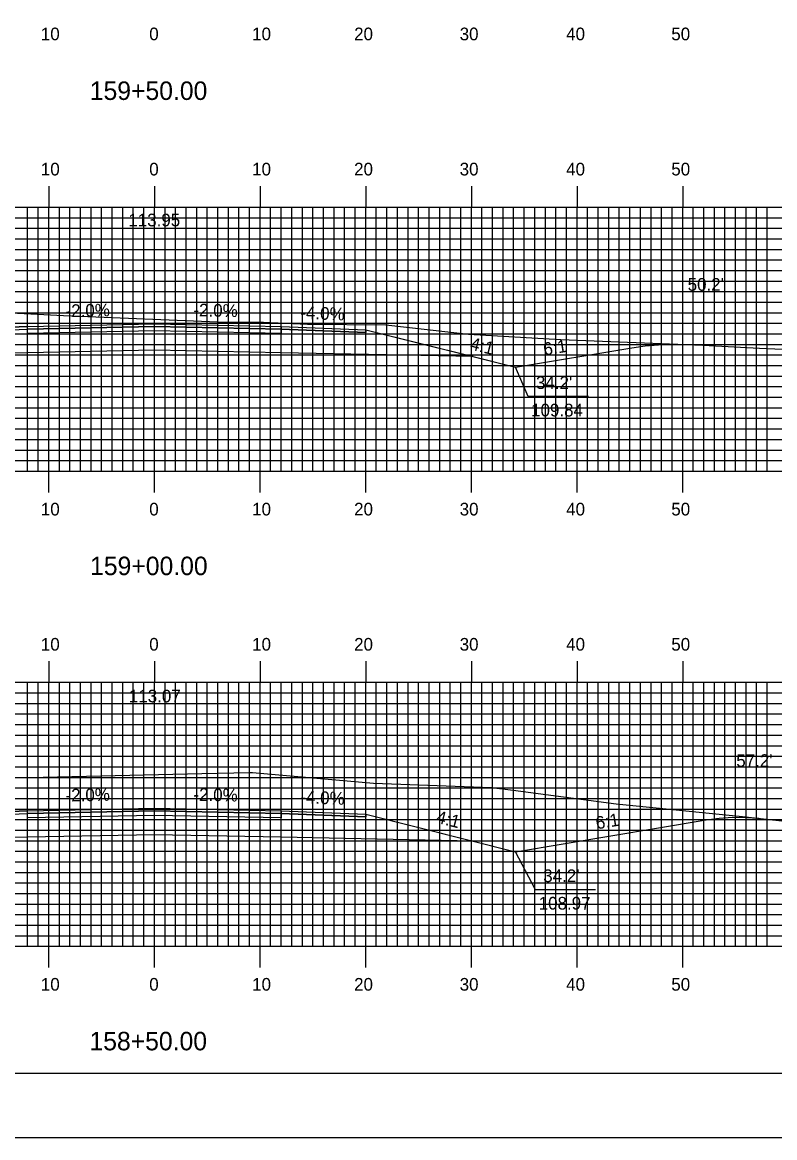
# Model space of a CAD drawing. Extents: x 1779893 to 1780236, y 442591 to 442811.
# Drawn here: x 1780045.9 to 1780117.1, y 442590.5 to 442696.2 of the extents above; entities that cross this region are included whole.
import ezdxf

# ---------------------------------------------------------------- set-up
doc = ezdxf.new("R2010")
doc.units = 0
for name, color, linetype in [('ANNOTATION', 7, 'Continuous'), ('BORDER', 7, 'Continuous'), ('D_Roadway_Centerline', 7, 'Continuous'), ('D_Roadway_Centerline_Text', 7, 'Continuous'), ('D_Roadway_Edge_Shoulder', 7, 'Continuous'), ('D_Roadway_Edge_TW', 7, 'Continuous'), ('D_Roadway_Pavement', 7, 'Continuous'), ('D_Roadway_SlopeLines', 7, 'Continuous'), ('D_Roadway_SubGrade', 7, 'Continuous'), ('D_Text_Standard', 7, 'Continuous'), ('H_V ANNOTATION', 7, 'Continuous'), ('MAJOR', 7, 'Continuous'), ('MINOR', 7, 'Continuous'), ('PLOT BOUNDARY', 7, 'Continuous'), ('S_Roadway_Centerline', 7, 'Continuous')]:
    doc.layers.add(name, color=color, linetype=linetype)

msp = doc.modelspace()

# ---------------------------------------------------------------- linework, layer by layer
at = {"layer": 'ANNOTATION'}
for points in [[(1780099.43, 442660.73), (1780093.74, 442660.73), (1780092.53, 442663.51)], [(1780100.12, 442614.02), (1780094.42, 442614.02), (1780092.53, 442617.63)]]:
    msp.add_lwpolyline(points, dxfattribs=at)
at = {"layer": 'BORDER'}
msp.add_lwpolyline([(1779908.76, 442596.67), (1780228.76, 442596.67), (1780228.76, 442806.67), (1779908.76, 442806.67)], close=True, dxfattribs=at)
at = {"layer": 'D_Roadway_Centerline'}
for points in [[(1779986.66, 442669.34), (1779987.91, 442669.32), (1779989.16, 442669.24), (1779990.41, 442669.11), (1779991.66, 442668.93), (1780024.18, 442663.51), (1780028.18, 442664.51), (1780038.36, 442667.05), (1780046.36, 442667.37), (1780058.36, 442667.61), (1780070.36, 442667.37), (1780078.36, 442667.05), (1780088.53, 442664.51), (1780092.53, 442663.51), (1780103.56, 442665.35), (1780104.81, 442665.52), (1780106.06, 442665.64), (1780107.31, 442665.68), (1780108.56, 442665.67)], [(1779987.48, 442623.37), (1779988.73, 442623.33), (1779989.98, 442623.24), (1779991.23, 442623.1), (1779992.48, 442622.92), (1780024.18, 442617.63), (1780028.18, 442618.63), (1780038.36, 442621.18), (1780046.36, 442621.5), (1780058.36, 442621.74), (1780070.36, 442621.5), (1780078.36, 442621.18), (1780088.53, 442618.63), (1780092.53, 442617.63), (1780110.57, 442620.64), (1780111.82, 442620.81), (1780113.07, 442620.89), (1780114.32, 442620.88), (1780115.57, 442620.79)]]:
    msp.add_lwpolyline(points, dxfattribs=at)
at = {"layer": 'D_Roadway_Edge_Shoulder'}
for points in [[(1780046.36, 442667.37), (1780038.36, 442667.05), (1780038.36, 442666.8), (1780046.36, 442667.12)], [(1780070.36, 442667.37), (1780078.36, 442667.05), (1780078.36, 442666.8), (1780070.36, 442667.12)], [(1780046.36, 442621.5), (1780038.36, 442621.18), (1780038.36, 442620.93), (1780046.36, 442621.25)], [(1780070.36, 442621.5), (1780078.36, 442621.18), (1780078.36, 442620.93), (1780070.36, 442621.25)]]:
    msp.add_lwpolyline(points, close=True, dxfattribs=at)
at = {"layer": 'D_Roadway_Edge_TW'}
for points in [[(1780046.36, 442667.12), (1780046.36, 442667.37), (1780058.36, 442667.61), (1780070.36, 442667.37), (1780070.36, 442667.12), (1780058.36, 442667.36)], [(1780046.36, 442621.25), (1780046.36, 442621.5), (1780058.36, 442621.74), (1780070.36, 442621.5), (1780070.36, 442621.25), (1780058.36, 442621.49)]]:
    msp.add_lwpolyline(points, close=True, dxfattribs=at)
at = {"layer": 'D_Roadway_Pavement'}
for points in [[(1780046.36, 442666.71), (1780046.36, 442667.12), (1780058.36, 442667.36), (1780070.36, 442667.12), (1780070.36, 442666.71), (1780058.36, 442666.95)], [(1780046.36, 442620.83), (1780046.36, 442621.25), (1780058.36, 442621.49), (1780070.36, 442621.25), (1780070.36, 442620.83), (1780058.36, 442621.07)]]:
    msp.add_lwpolyline(points, close=True, dxfattribs=at)
at = {"layer": 'D_Roadway_SlopeLines'}
for points in [[(1780078.36, 442667.05), (1780092.53, 442663.51)], [(1780092.53, 442663.51), (1780103.56, 442665.35), (1780104.81, 442665.52), (1780106.06, 442665.64), (1780107.31, 442665.68), (1780108.56, 442665.67)], [(1780078.36, 442621.18), (1780092.53, 442617.63)], [(1780092.53, 442617.63), (1780110.57, 442620.64), (1780111.82, 442620.81), (1780113.07, 442620.89), (1780114.32, 442620.88), (1780115.57, 442620.79)]]:
    msp.add_lwpolyline(points, dxfattribs=at)
at = {"layer": 'D_Roadway_SubGrade'}
for points in [[(1780046.36, 442664.87), (1780028.18, 442664.51), (1780038.36, 442667.05), (1780038.36, 442666.8), (1780046.36, 442667.12), (1780058.36, 442667.36), (1780070.36, 442667.12), (1780078.36, 442666.8), (1780078.36, 442667.05), (1780088.53, 442664.51), (1780070.36, 442664.87), (1780058.36, 442665.11)], [(1780046.36, 442619), (1780028.18, 442618.63), (1780038.36, 442621.18), (1780038.36, 442620.93), (1780046.36, 442621.25), (1780058.36, 442621.49), (1780070.36, 442621.25), (1780078.36, 442620.93), (1780078.36, 442621.18), (1780088.53, 442618.63), (1780070.36, 442619), (1780058.36, 442619.24)]]:
    msp.add_lwpolyline(points, close=True, dxfattribs=at)
at = {"layer": 'MAJOR'}
for p, q in [((1780048.36, 442680.67), (1780048.36, 442678.67)), ((1780058.36, 442680.67), (1780058.36, 442678.67)), ((1780068.36, 442680.67), (1780068.36, 442678.67)), ((1780078.36, 442680.67), (1780078.36, 442678.67)), ((1780088.36, 442680.67), (1780088.36, 442678.67)), ((1780098.36, 442680.67), (1780098.36, 442678.67)), ((1780108.36, 442680.67), (1780108.36, 442678.67)), ((1779918.36, 442678.67), (1780198.36, 442678.67)), ((1779918.36, 442678.67), (1780198.36, 442678.67)), ((1780048.36, 442653.67), (1780048.36, 442678.67)), ((1780058.36, 442653.67), (1780058.36, 442678.67)), ((1780068.36, 442653.67), (1780068.36, 442678.67)), ((1780078.36, 442653.67), (1780078.36, 442678.67)), ((1780088.36, 442653.67), (1780088.36, 442678.67)), ((1780098.36, 442653.67), (1780098.36, 442678.67)), ((1780108.36, 442653.67), (1780108.36, 442678.67)), ((1779918.36, 442673.67), (1780198.36, 442673.67)), ((1779918.36, 442668.67), (1780198.36, 442668.67)), ((1779918.36, 442663.67), (1780198.36, 442663.67)), ((1779918.36, 442658.67), (1780198.36, 442658.67)), ((1779918.36, 442653.67), (1780198.36, 442653.67)), ((1779918.36, 442653.67), (1780198.36, 442653.67)), ((1780048.36, 442651.66), (1780048.36, 442653.67)), ((1780058.36, 442651.66), (1780058.36, 442653.67)), ((1780068.36, 442651.66), (1780068.36, 442653.67)), ((1780078.36, 442651.66), (1780078.36, 442653.67)), ((1780088.36, 442651.66), (1780088.36, 442653.67)), ((1780098.36, 442651.66), (1780098.36, 442653.67)), ((1780108.36, 442651.66), (1780108.36, 442653.67)), ((1780048.36, 442635.67), (1780048.36, 442633.67)), ((1780058.36, 442635.67), (1780058.36, 442633.67)), ((1780068.36, 442635.67), (1780068.36, 442633.67)), ((1780078.36, 442635.67), (1780078.36, 442633.67)), ((1780088.36, 442635.67), (1780088.36, 442633.67)), ((1780098.36, 442635.67), (1780098.36, 442633.67)), ((1780108.36, 442635.67), (1780108.36, 442633.67)), ((1779918.36, 442633.67), (1780198.36, 442633.67)), ((1779918.36, 442633.67), (1780198.36, 442633.67)), ((1780048.36, 442608.67), (1780048.36, 442633.67)), ((1780058.36, 442608.67), (1780058.36, 442633.67)), ((1780068.36, 442608.67), (1780068.36, 442633.67)), ((1780078.36, 442608.67), (1780078.36, 442633.67)), ((1780088.36, 442608.67), (1780088.36, 442633.67)), ((1780098.36, 442608.67), (1780098.36, 442633.67)), ((1780108.36, 442608.67), (1780108.36, 442633.67)), ((1779918.36, 442628.67), (1780198.36, 442628.67)), ((1779918.36, 442623.67), (1780198.36, 442623.67)), ((1779918.36, 442618.67), (1780198.36, 442618.67)), ((1779918.36, 442613.67), (1780198.36, 442613.67)), ((1779918.36, 442608.67), (1780198.36, 442608.67)), ((1779918.36, 442608.67), (1780198.36, 442608.67)), ((1780048.36, 442606.66), (1780048.36, 442608.67)), ((1780058.36, 442606.66), (1780058.36, 442608.67)), ((1780068.36, 442606.66), (1780068.36, 442608.67)), ((1780078.36, 442606.66), (1780078.36, 442608.67)), ((1780088.36, 442606.66), (1780088.36, 442608.67)), ((1780098.36, 442606.66), (1780098.36, 442608.67)), ((1780108.36, 442606.66), (1780108.36, 442608.67))]:
    msp.add_line(p, q, dxfattribs=at)
at = {"layer": 'MINOR'}
for p, q in [((1780046.36, 442653.67), (1780046.36, 442678.67)), ((1780047.36, 442653.67), (1780047.36, 442678.67)), ((1780049.36, 442653.67), (1780049.36, 442678.67)), ((1780050.36, 442653.67), (1780050.36, 442678.67)), ((1780051.36, 442653.67), (1780051.36, 442678.67)), ((1780052.36, 442653.67), (1780052.36, 442678.67)), ((1780053.36, 442653.67), (1780053.36, 442678.67)), ((1780054.36, 442653.67), (1780054.36, 442678.67)), ((1780055.36, 442653.67), (1780055.36, 442678.67)), ((1780056.36, 442653.67), (1780056.36, 442678.67)), ((1780057.36, 442653.67), (1780057.36, 442678.67)), ((1780059.36, 442653.67), (1780059.36, 442678.67)), ((1780060.36, 442653.67), (1780060.36, 442678.67)), ((1780061.36, 442653.67), (1780061.36, 442678.67)), ((1780062.36, 442653.67), (1780062.36, 442678.67)), ((1780063.36, 442653.67), (1780063.36, 442678.67)), ((1780064.36, 442653.67), (1780064.36, 442678.67)), ((1780065.36, 442653.67), (1780065.36, 442678.67)), ((1780066.36, 442653.67), (1780066.36, 442678.67)), ((1780067.36, 442653.67), (1780067.36, 442678.67)), ((1780069.36, 442653.67), (1780069.36, 442678.67)), ((1780070.36, 442653.67), (1780070.36, 442678.67)), ((1780071.36, 442653.67), (1780071.36, 442678.67)), ((1780072.36, 442653.67), (1780072.36, 442678.67)), ((1780073.36, 442653.67), (1780073.36, 442678.67)), ((1780074.36, 442653.67), (1780074.36, 442678.67)), ((1780075.36, 442653.67), (1780075.36, 442678.67)), ((1780076.36, 442653.67), (1780076.36, 442678.67)), ((1780077.36, 442653.67), (1780077.36, 442678.67)), ((1780079.36, 442653.67), (1780079.36, 442678.67)), ((1780080.36, 442653.67), (1780080.36, 442678.67)), ((1780081.36, 442653.67), (1780081.36, 442678.67)), ((1780082.36, 442653.67), (1780082.36, 442678.67)), ((1780083.36, 442653.67), (1780083.36, 442678.67)), ((1780084.36, 442653.67), (1780084.36, 442678.67)), ((1780085.36, 442653.67), (1780085.36, 442678.67)), ((1780086.36, 442653.67), (1780086.36, 442678.67)), ((1780087.36, 442653.67), (1780087.36, 442678.67)), ((1780089.36, 442653.67), (1780089.36, 442678.67)), ((1780090.36, 442653.67), (1780090.36, 442678.67)), ((1780091.36, 442653.67), (1780091.36, 442678.67)), ((1780092.36, 442653.67), (1780092.36, 442678.67)), ((1780093.36, 442653.67), (1780093.36, 442678.67)), ((1780094.36, 442653.67), (1780094.36, 442678.67)), ((1780095.36, 442653.67), (1780095.36, 442678.67)), ((1780096.36, 442653.67), (1780096.36, 442678.67)), ((1780097.36, 442653.67), (1780097.36, 442678.67)), ((1780099.36, 442653.67), (1780099.36, 442678.67)), ((1780100.36, 442653.67), (1780100.36, 442678.67)), ((1780101.36, 442653.67), (1780101.36, 442678.67)), ((1780102.36, 442653.67), (1780102.36, 442678.67)), ((1780103.36, 442653.67), (1780103.36, 442678.67)), ((1780104.36, 442653.67), (1780104.36, 442678.67)), ((1780105.36, 442653.67), (1780105.36, 442678.67)), ((1780106.36, 442653.67), (1780106.36, 442678.67)), ((1780107.36, 442653.67), (1780107.36, 442678.67)), ((1780109.36, 442653.67), (1780109.36, 442678.67)), ((1780110.36, 442653.67), (1780110.36, 442678.67)), ((1780111.36, 442653.67), (1780111.36, 442678.67)), ((1780112.36, 442653.67), (1780112.36, 442678.67)), ((1780113.36, 442653.67), (1780113.36, 442678.67)), ((1780114.36, 442653.67), (1780114.36, 442678.67)), ((1780115.36, 442653.67), (1780115.36, 442678.67)), ((1780116.36, 442653.67), (1780116.36, 442678.67)), ((1779918.36, 442677.67), (1780198.36, 442677.67)), ((1779918.36, 442676.67), (1780198.36, 442676.67)), ((1779918.36, 442675.67), (1780198.36, 442675.67)), ((1779918.36, 442674.67), (1780198.36, 442674.67)), ((1779918.36, 442672.67), (1780198.36, 442672.67)), ((1779918.36, 442671.67), (1780198.36, 442671.67)), ((1779918.36, 442670.67), (1780198.36, 442670.67)), ((1779918.36, 442669.67), (1780198.36, 442669.67)), ((1779918.36, 442667.67), (1780198.36, 442667.67)), ((1779918.36, 442666.67), (1780198.36, 442666.67)), ((1779918.36, 442665.67), (1780198.36, 442665.67)), ((1779918.36, 442664.67), (1780198.36, 442664.67)), ((1779918.36, 442662.67), (1780198.36, 442662.67)), ((1779918.36, 442661.67), (1780198.36, 442661.67)), ((1779918.36, 442660.67), (1780198.36, 442660.67)), ((1779918.36, 442659.67), (1780198.36, 442659.67)), ((1779918.36, 442657.67), (1780198.36, 442657.67)), ((1779918.36, 442656.67), (1780198.36, 442656.67)), ((1779918.36, 442655.67), (1780198.36, 442655.67)), ((1779918.36, 442654.67), (1780198.36, 442654.67)), ((1780046.36, 442608.67), (1780046.36, 442633.67)), ((1780047.36, 442608.67), (1780047.36, 442633.67)), ((1780049.36, 442608.67), (1780049.36, 442633.67)), ((1780050.36, 442608.67), (1780050.36, 442633.67)), ((1780051.36, 442608.67), (1780051.36, 442633.67)), ((1780052.36, 442608.67), (1780052.36, 442633.67)), ((1780053.36, 442608.67), (1780053.36, 442633.67)), ((1780054.36, 442608.67), (1780054.36, 442633.67)), ((1780055.36, 442608.67), (1780055.36, 442633.67)), ((1780056.36, 442608.67), (1780056.36, 442633.67)), ((1780057.36, 442608.67), (1780057.36, 442633.67)), ((1780059.36, 442608.67), (1780059.36, 442633.67)), ((1780060.36, 442608.67), (1780060.36, 442633.67)), ((1780061.36, 442608.67), (1780061.36, 442633.67)), ((1780062.36, 442608.67), (1780062.36, 442633.67)), ((1780063.36, 442608.67), (1780063.36, 442633.67)), ((1780064.36, 442608.67), (1780064.36, 442633.67)), ((1780065.36, 442608.67), (1780065.36, 442633.67)), ((1780066.36, 442608.67), (1780066.36, 442633.67)), ((1780067.36, 442608.67), (1780067.36, 442633.67)), ((1780069.36, 442608.67), (1780069.36, 442633.67)), ((1780070.36, 442608.67), (1780070.36, 442633.67)), ((1780071.36, 442608.67), (1780071.36, 442633.67)), ((1780072.36, 442608.67), (1780072.36, 442633.67)), ((1780073.36, 442608.67), (1780073.36, 442633.67)), ((1780074.36, 442608.67), (1780074.36, 442633.67)), ((1780075.36, 442608.67), (1780075.36, 442633.67)), ((1780076.36, 442608.67), (1780076.36, 442633.67)), ((1780077.36, 442608.67), (1780077.36, 442633.67)), ((1780079.36, 442608.67), (1780079.36, 442633.67)), ((1780080.36, 442608.67), (1780080.36, 442633.67)), ((1780081.36, 442608.67), (1780081.36, 442633.67)), ((1780082.36, 442608.67), (1780082.36, 442633.67)), ((1780083.36, 442608.67), (1780083.36, 442633.67)), ((1780084.36, 442608.67), (1780084.36, 442633.67)), ((1780085.36, 442608.67), (1780085.36, 442633.67)), ((1780086.36, 442608.67), (1780086.36, 442633.67)), ((1780087.36, 442608.67), (1780087.36, 442633.67)), ((1780089.36, 442608.67), (1780089.36, 442633.67)), ((1780090.36, 442608.67), (1780090.36, 442633.67)), ((1780091.36, 442608.67), (1780091.36, 442633.67)), ((1780092.36, 442608.67), (1780092.36, 442633.67)), ((1780093.36, 442608.67), (1780093.36, 442633.67)), ((1780094.36, 442608.67), (1780094.36, 442633.67)), ((1780095.36, 442608.67), (1780095.36, 442633.67)), ((1780096.36, 442608.67), (1780096.36, 442633.67)), ((1780097.36, 442608.67), (1780097.36, 442633.67)), ((1780099.36, 442608.67), (1780099.36, 442633.67)), ((1780100.36, 442608.67), (1780100.36, 442633.67)), ((1780101.36, 442608.67), (1780101.36, 442633.67)), ((1780102.36, 442608.67), (1780102.36, 442633.67)), ((1780103.36, 442608.67), (1780103.36, 442633.67)), ((1780104.36, 442608.67), (1780104.36, 442633.67)), ((1780105.36, 442608.67), (1780105.36, 442633.67)), ((1780106.36, 442608.67), (1780106.36, 442633.67)), ((1780107.36, 442608.67), (1780107.36, 442633.67)), ((1780109.36, 442608.67), (1780109.36, 442633.67)), ((1780110.36, 442608.67), (1780110.36, 442633.67)), ((1780111.36, 442608.67), (1780111.36, 442633.67)), ((1780112.36, 442608.67), (1780112.36, 442633.67)), ((1780113.36, 442608.67), (1780113.36, 442633.67)), ((1780114.36, 442608.67), (1780114.36, 442633.67)), ((1780115.36, 442608.67), (1780115.36, 442633.67)), ((1780116.36, 442608.67), (1780116.36, 442633.67)), ((1779918.36, 442632.67), (1780198.36, 442632.67)), ((1779918.36, 442631.67), (1780198.36, 442631.67)), ((1779918.36, 442630.67), (1780198.36, 442630.67)), ((1779918.36, 442629.67), (1780198.36, 442629.67)), ((1779918.36, 442627.67), (1780198.36, 442627.67)), ((1779918.36, 442626.67), (1780198.36, 442626.67)), ((1779918.36, 442625.67), (1780198.36, 442625.67)), ((1779918.36, 442624.67), (1780198.36, 442624.67)), ((1779918.36, 442622.67), (1780198.36, 442622.67)), ((1779918.36, 442621.67), (1780198.36, 442621.67)), ((1779918.36, 442620.67), (1780198.36, 442620.67)), ((1779918.36, 442619.67), (1780198.36, 442619.67)), ((1779918.36, 442617.67), (1780198.36, 442617.67)), ((1779918.36, 442616.67), (1780198.36, 442616.67)), ((1779918.36, 442615.67), (1780198.36, 442615.67)), ((1779918.36, 442614.67), (1780198.36, 442614.67)), ((1779918.36, 442612.67), (1780198.36, 442612.67)), ((1779918.36, 442611.67), (1780198.36, 442611.67)), ((1779918.36, 442610.67), (1780198.36, 442610.67)), ((1779918.36, 442609.67), (1780198.36, 442609.67))]:
    msp.add_line(p, q, dxfattribs=at)
at = {"layer": 'PLOT BOUNDARY'}
msp.add_lwpolyline([(1779892.57, 442590.55), (1780232.57, 442590.55), (1780232.57, 442810.55), (1779892.57, 442810.55)], close=True, dxfattribs=at)
at = {"layer": 'S_Roadway_Centerline'}
for points in [[(1779977.17, 442669.48), (1779983.58, 442669.33), (1779995.57, 442669.36), (1779997.14, 442669.33), (1779998.34, 442669.33), (1779999.6, 442669.42), (1780010.11, 442669.81), (1780019.2, 442669.6), (1780021.97, 442669.33), (1780024.59, 442669.34), (1780033.79, 442669.33), (1780043.51, 442668.72), (1780049.74, 442668.41), (1780065.11, 442667.79), (1780068.68, 442667.78), (1780072.85, 442667.59), (1780080.27, 442667.53), (1780088.09, 442666.65), (1780096.82, 442666.12), (1780110.25, 442665.6), (1780115.63, 442665.3), (1780120.75, 442665.09)], [(1779976.32, 442623.59), (1779986.82, 442623.38), (1779997.03, 442623.23), (1779999.13, 442623.22), (1780009.2, 442623.03), (1780020.4, 442623.35), (1780023.1, 442623.4), (1780042.65, 442624.54), (1780043.68, 442624.6), (1780062.86, 442625.04), (1780067.38, 442625.14), (1780067.5, 442625.13), (1780067.64, 442625.13), (1780079.11, 442624.13), (1780090.25, 442623.7), (1780092.32, 442623.47), (1780102.07, 442622.16), (1780114.01, 442620.96), (1780125.74, 442619.66)]]:
    msp.add_lwpolyline(points, dxfattribs=at)

# ---------------------------------------------------------------- texts
at = {"layer": 'ANNOTATION'}
for s, rotation, p in [('-2.0%', 1.1458, (1780049.96, 442668.25)), ('-2.0%', 358.8542, (1780062.04, 442668.34)), ('-4.0%', 357.7094, (1780072.15, 442668.1)), ('4:1', 345.9638, (1780088.16, 442665.21)), ('6:1', 9.4625, (1780095.27, 442664.61)), ('-2.0%', 1.1458, (1780049.96, 442622.37)), ('-2.0%', 358.8542, (1780062.04, 442622.46)), ('-4.0%', 357.7094, (1780072.15, 442622.23)), ('4:1', 345.9638, (1780084.95, 442620.39)), ('6:1', 9.4625, (1780100.23, 442619.74))]:
    msp.add_text(s, height=1.2, rotation=rotation, dxfattribs=at).set_placement(p)
for s, p in [("34.2'", (1780094.47, 442661.45)), ('109.84', (1780094.01, 442658.85)), ("34.2'", (1780095.16, 442614.75)), ('108.97', (1780094.73, 442612.15))]:
    msp.add_text(s, height=1.2, dxfattribs=at).set_placement(p)
at = {"layer": 'D_Roadway_Centerline'}
for s, p in [('C', (1780058.35, 442667.61)), ('L', (1780058.36, 442667.61)), ('C', (1780058.35, 442621.74)), ('L', (1780058.36, 442621.73))]:
    msp.add_text(s, height=0.0146, dxfattribs=at).set_placement(p)
at = {"layer": 'D_Roadway_Centerline_Text'}
for s, p in [('113.95', (1780055.89, 442676.85)), ('113.07', (1780055.94, 442631.77))]:
    msp.add_text(s, height=1.2, dxfattribs=at).set_placement(p)
at = {"layer": 'D_Text_Standard'}
for s, p in [("50.2'", (1780108.83, 442670.75)), ("57.2'", (1780113.43, 442625.66))]:
    msp.add_text(s, height=1.2, dxfattribs=at).set_placement(p)
at = {"layer": 'H_V ANNOTATION'}
for s, height, p in [('10', 1.2, (1780047.61, 442694.47)), ('0', 1.2, (1780057.87, 442694.47)), ('10', 1.2, (1780067.61, 442694.47)), ('20', 1.2, (1780077.26, 442694.47)), ('30', 1.2, (1780087.25, 442694.47)), ('40', 1.2, (1780097.33, 442694.47)), ('50', 1.2, (1780107.28, 442694.47)), ('159+50.00', 1.75, (1780052.24, 442688.82)), ('10', 1.2, (1780047.61, 442681.67)), ('0', 1.2, (1780057.87, 442681.67)), ('10', 1.2, (1780067.61, 442681.67)), ('20', 1.2, (1780077.26, 442681.67)), ('30', 1.2, (1780087.25, 442681.67)), ('40', 1.2, (1780097.33, 442681.67)), ('50', 1.2, (1780107.28, 442681.67)), ('10', 1.2, (1780047.61, 442649.47)), ('0', 1.2, (1780057.87, 442649.47)), ('10', 1.2, (1780067.61, 442649.47)), ('20', 1.2, (1780077.26, 442649.47)), ('30', 1.2, (1780087.25, 442649.47)), ('40', 1.2, (1780097.33, 442649.47)), ('50', 1.2, (1780107.28, 442649.47)), ('159+00.00', 1.75, (1780052.27, 442643.82)), ('10', 1.2, (1780047.61, 442636.67)), ('0', 1.2, (1780057.87, 442636.67)), ('10', 1.2, (1780067.61, 442636.67)), ('20', 1.2, (1780077.26, 442636.67)), ('30', 1.2, (1780087.25, 442636.67)), ('40', 1.2, (1780097.33, 442636.67)), ('50', 1.2, (1780107.28, 442636.67)), ('10', 1.2, (1780047.61, 442604.47)), ('0', 1.2, (1780057.87, 442604.47)), ('10', 1.2, (1780067.61, 442604.47)), ('20', 1.2, (1780077.26, 442604.47)), ('30', 1.2, (1780087.25, 442604.47)), ('40', 1.2, (1780097.33, 442604.47)), ('50', 1.2, (1780107.28, 442604.47)), ('158+50.00', 1.75, (1780052.21, 442598.82))]:
    msp.add_text(s, height=height, dxfattribs=at).set_placement(p)

doc.saveas('drawing.dxf')
